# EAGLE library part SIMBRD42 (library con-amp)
AMP connector
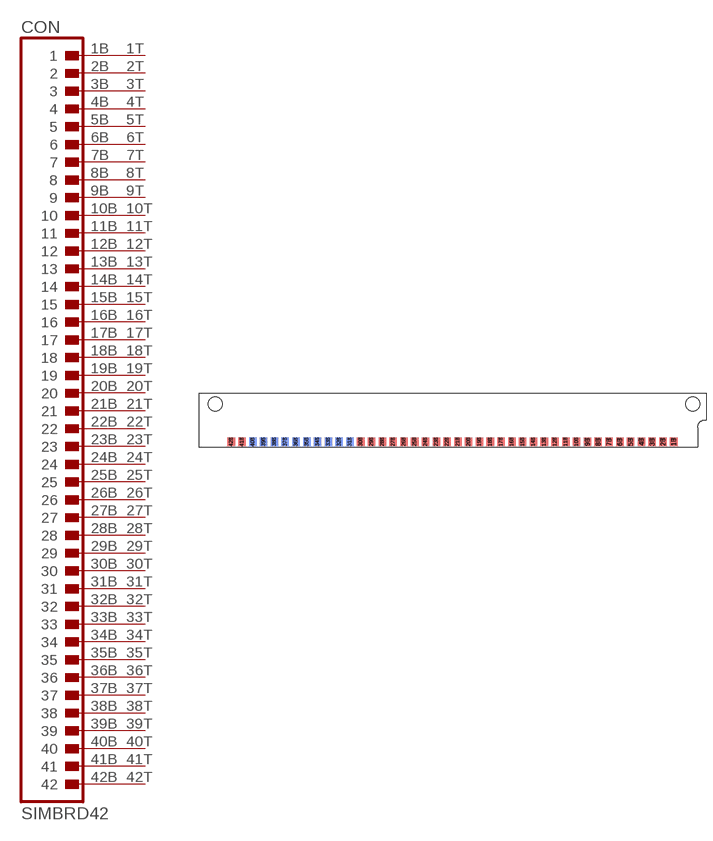
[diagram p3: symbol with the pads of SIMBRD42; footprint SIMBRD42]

Designator prefix CON

## SIMBRD42 (OC_FARNELL: unknown; OC_NEWARK: unknown)  [SIMBRD42]
1B  1  pas
1T  A1  pas
2B  2  pas
2T  A2  pas
3B  3  pas
3T  A3  pas
4B  4  pas
4T  A4  pas
5B  5  pas
5T  A5  pas
6B  6  pas
6T  A6  pas
7B  7  pas
7T  A7  pas
8B  8  pas
8T  A8  pas
9B  9  pas
9T  A9  pas
10B  10  pas
10T  A10  pas
11B  11  pas
11T  A11  pas
12B  12  pas
12T  A12  pas
13B  13  pas
13T  A13  pas
14B  14  pas
14T  A14  pas
15B  15  pas
15T  A15  pas
16B  16  pas
16T  A16  pas
17B  17  pas
17T  A17  pas
18B  18  pas
18T  A18  pas
19B  19  pas
19T  A19  pas
20B  20  pas
20T  A20  pas
21B  21  pas
21T  A21  pas
22B  22  pas
22T  A22  pas
23B  23  pas
23T  A23  pas
24B  24  pas
24T  A24  pas
25B  25  pas
25T  A25  pas
26B  26  pas
26T  A26  pas
27B  27  pas
27T  A27  pas
28B  28  pas
28T  A28  pas
29B  29  pas
29T  A29  pas
30B  30  pas
30T  A30  pas
31B  31  pas
31T  A31  pas
32B  32  pas
32T  A32  pas
33B  33  pas
33T  A33  pas
34B  34  pas
34T  A34  pas
35B  35  pas
35T  A35  pas
36B  36  pas
36T  A36  pas
37B  37  pas
37T  A37  pas
38B  38  pas
38T  A38  pas
39B  39  pas
39T  A39  pas
40B  40  pas
40T  A40  pas
41B  41  pas
41T  A41  pas
42B  42  pas
42T  A42  pas

## Footprint SIMBRD42 (pad centres in mm)
SIMM Modul
smd 1.778 x 2.032 bottom: 1B 53.34,-6.35; 2B 50.8,-6.35; 3B 48.26,-6.35; 4B 45.72,-6.35; 5B 43.18,-6.35; 6B 40.64,-6.35; 7B 38.1,-6.35; 8B 35.56,-6.35; 9B 33.02,-6.35; 10B 30.48,-6.35; 11B 27.94,-6.35; 12B 25.4,-6.35; 13B 22.86,-6.35; 14B 20.32,-6.35; 15B 17.78,-6.35; 16B 15.24,-6.35; 17B 12.7,-6.35; 18B 10.16,-6.35; 19B 7.62,-6.35; 20B 5.08,-6.35; 21B 2.54,-6.35; 22B 0,-6.35; 23B -2.54,-6.35; 24B -5.08,-6.35; 25B -7.62,-6.35; 26B -10.16,-6.35; 27B -12.7,-6.35; 28B -15.24,-6.35; 29B -17.78,-6.35; 30B -20.32,-6.35; 31B -22.86,-6.35; 32B -25.4,-6.35; 33B -27.94,-6.35; 34B -30.48,-6.35; 35B -33.02,-6.35; 36B -35.56,-6.35; 37B -38.1,-6.35; 38B -40.64,-6.35; 39B -43.18,-6.35; 40B -45.72,-6.35; 41B -48.26,-6.35; 42B -50.8,-6.35
smd 1.778 x 2.032: 1T 53.34,-6.35; 2T 50.8,-6.35; 3T 48.26,-6.35; 4T 45.72,-6.35; 5T 43.18,-6.35; 6T 40.64,-6.35; 7T 38.1,-6.35; 8T 35.56,-6.35; 9T 33.02,-6.35; 10T 30.48,-6.35; 11T 27.94,-6.35; 12T 25.4,-6.35; 13T 22.86,-6.35; 14T 20.32,-6.35; 15T 17.78,-6.35; 16T 15.24,-6.35; 17T 12.7,-6.35; 18T 10.16,-6.35; 19T 7.62,-6.35; 20T 5.08,-6.35; 21T 2.54,-6.35; 22T 0,-6.35; 23T -2.54,-6.35; 24T -5.08,-6.35; 25T -7.62,-6.35; 26T -10.16,-6.35; 27T -12.7,-6.35; 28T -15.24,-6.35; 29T -17.78,-6.35; 30T -20.32,-6.35; 31T -22.86,-6.35; 32T -25.4,-6.35; 33T -27.94,-6.35; 34T -30.48,-6.35; 35T -33.02,-6.35; 36T -35.56,-6.35; 37T -38.1,-6.35; 38T -40.64,-6.35; 39T -43.18,-6.35; 40T -45.72,-6.35; 41T -48.26,-6.35; 42T -50.8,-6.35
hole 3.302 at -54.61,2.54
hole 3.302 at 57.785,2.54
